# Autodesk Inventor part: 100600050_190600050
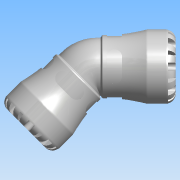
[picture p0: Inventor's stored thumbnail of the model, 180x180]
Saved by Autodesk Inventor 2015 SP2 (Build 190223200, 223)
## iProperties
Created: 2016-12
Part Number: 100600050_190600050
Material: PVC-Piping
Description: PLASSON 45° ELBOW 50-50 SERIES 1
Document SubType Name: Modeling
Designer: KIM
Mass: 664.223 g
Surface Area: 733.008 cm^2
Volume: 474.445 cm^3
Density: 1.4 g/cm^3
Appearance: Smooth - White
Author: KIM
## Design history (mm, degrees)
derived "1006.ipt"
feature "Solid1::1006.ipt"
tag "TaggingFeature1"
body "Solid1"
other parameters: "d1" = 33.18, "d3" = 62.5, "d4" = 85, "d8" = 72.25, "d13" = 9, "d14" = 9, "d15" = 0, "d17" = 360 deg, "d19" = 8 deg, "d20" = 1, "d21" = 1, "d22" = 8 deg, "d24" = 0, "d26" = 360 deg, "d33" = 8.5, "d43" = 66.3, "d51" = 0.85, "d54" = 17.5, "d55" = 11, "d57" = 17.64, "d58" = 0, "d74" = 0, "d77" = 4.16667, "d78" = 79, "d82" = 1, "d115" = 360 deg, "d207" = 90 deg, "d228" = 14.875, "d247" = 1.7, "d248" = 4.74, "d268" = 15.1725, "d269" = 4.55175, "d277" = 135 deg, "d279" = 4.55175, "d280" = 135 deg, "d281" = 0, "d282" = 0, "E_" = 85, "l_" = 79, "d9" = 11.25, "d11" = 85, "d12" = 62.5
